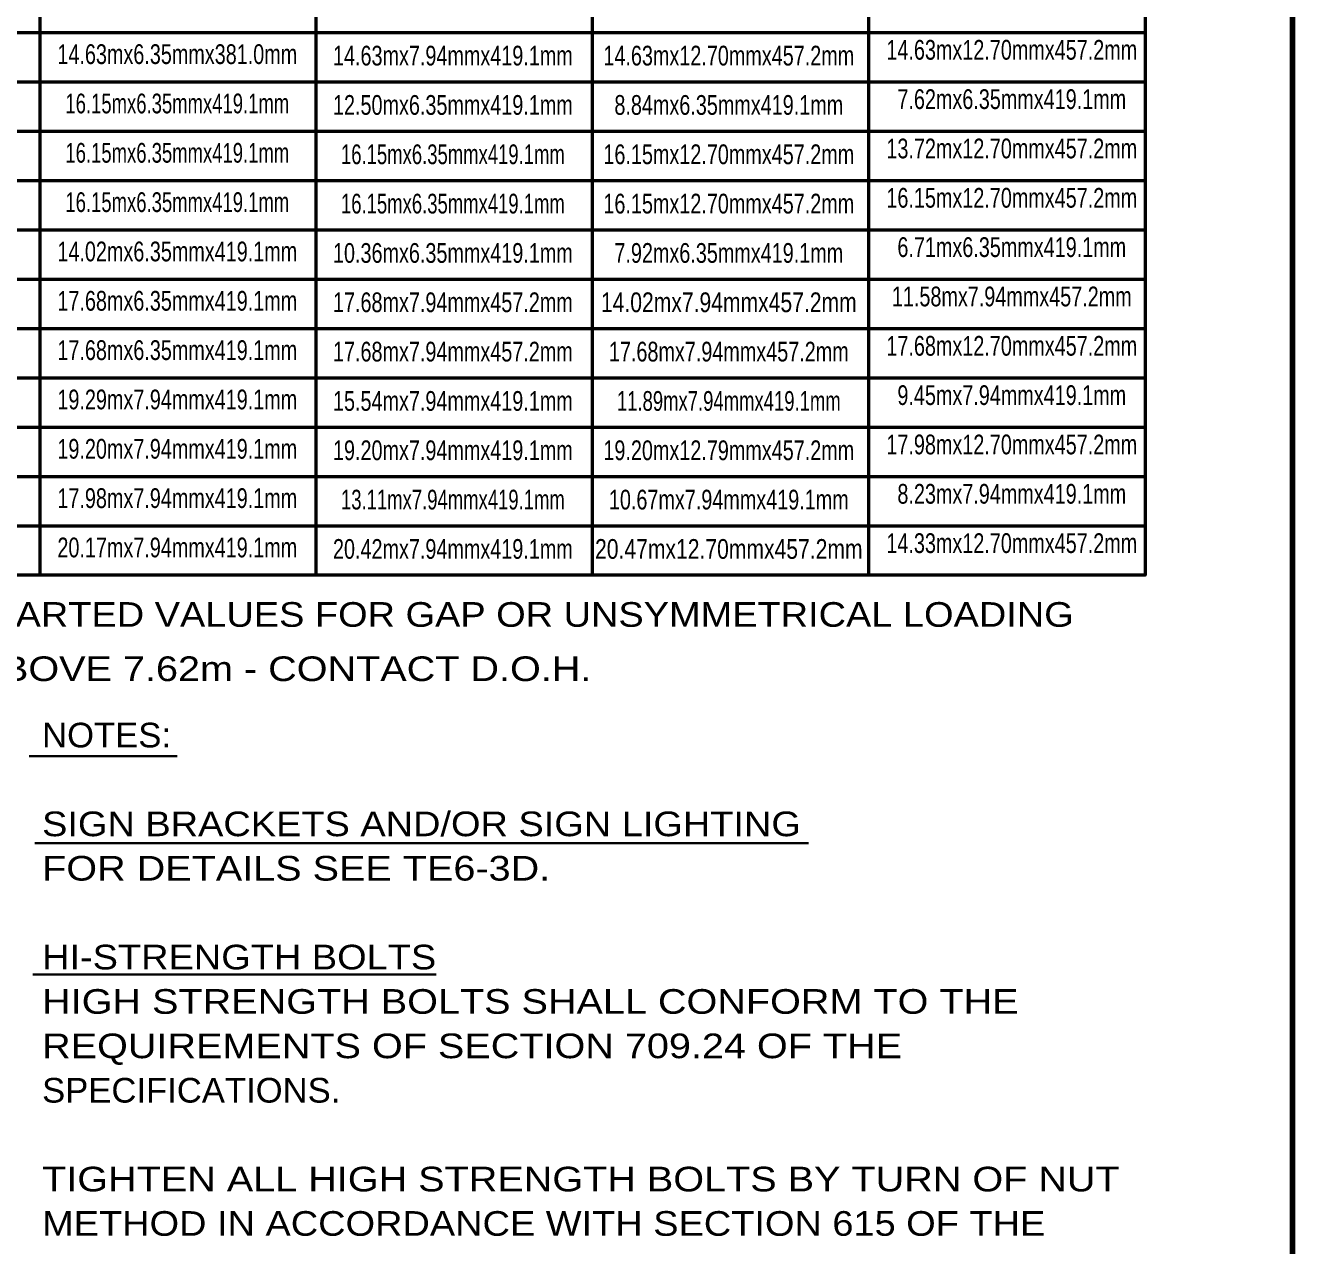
# Model space of a CAD drawing. Extents: x -34 to 822, y -23 to 521.
# Drawn here: x 660.8 to 814.9, y 213.8 to 362.2 of the extents above; entities that cross this region are included whole.
import ezdxf
from ezdxf.enums import TextEntityAlignment as Align

# ---------------------------------------------------------------- set-up
doc = ezdxf.new("R2010")
doc.units = 0
doc.header["$LTSCALE"] = 1.2
doc.layers.add('1', color=7, linetype='Continuous', lineweight=35)

msp = doc.modelspace()

# ---------------------------------------------------------------- linework, layer by layer
at = {"layer": '1', "lineweight": 158}
msp.add_line((814.9, -11.36), (814.9, 514.74), dxfattribs=at)
at = {"layer": '1', "lineweight": 13}
msp.add_line((814.9, -11.36), (814.9, 514.74), dxfattribs=at)
at = {"layer": '1', "lineweight": 53}
for p, q in [((662.554, 295.349), (662.554, 458.549)), ((696.154, 295.349), (696.154, 458.549)), ((729.754, 295.349), (729.754, 458.549)), ((763.354, 295.349), (763.354, 458.549)), ((595.354, 361.349), (796.954, 361.349)), ((577.354, 355.349), (796.954, 355.349)), ((595.354, 349.349), (796.954, 349.349)), ((595.354, 343.349), (796.954, 343.349)), ((577.354, 337.349), (796.954, 337.349)), ((595.354, 331.349), (796.954, 331.349)), ((595.354, 325.349), (796.954, 325.349)), ((577.354, 319.349), (796.954, 319.349)), ((595.354, 313.349), (796.954, 313.349)), ((577.354, 307.349), (796.954, 307.349)), ((595.354, 301.349), (796.954, 301.349))]:
    msp.add_line(p, q, dxfattribs=at)
at = {"layer": '1'}
for p, q in [((661.23, 273.35), (679.232, 273.35)), ((661.905, 262.77), (756.005, 262.77)), ((661.68, 246.788), (710.736, 246.788))]:
    msp.add_line(p, q, dxfattribs=at)
at = {"layer": '1', "lineweight": 53}
msp.add_lwpolyline([(577.354, 482.549), (796.954, 482.549), (796.954, 295.349), (577.354, 295.349)], close=True, dxfattribs=at)

# ---------------------------------------------------------------- texts
at = {"layer": '1'}
for s, width, p in [('14.63mx6.35mmx381.0mm', 0.75, (679.25, 357.518)), ('14.63mx7.94mmx419.1mm', 0.75, (712.766, 357.338)), ('14.63mx12.70mmx457.2mm', 0.75, (746.324, 357.338)), ('14.63mx12.70mmx457.2mm', 0.75, (780.742, 358.045)), ('16.15mx6.35mmx419.1mm', 0.7, (679.25, 351.518)), ('12.50mx6.35mmx419.1mm', 0.75, (712.766, 351.338)), ('8.84mx6.35mmx419.1mm', 0.75, (746.324, 351.338)), ('7.62mx6.35mmx419.1mm', 0.75, (780.742, 352.045)), ('13.72mx12.70mmx457.2mm', 0.75, (780.742, 346.045)), ('16.15mx6.35mmx419.1mm', 0.7, (679.25, 345.518)), ('16.15mx6.35mmx419.1mm', 0.7, (712.766, 345.338)), ('16.15mx12.70mmx457.2mm', 0.75, (746.324, 345.338)), ('16.15mx12.70mmx457.2mm', 0.75, (780.742, 340.045)), ('16.15mx6.35mmx419.1mm', 0.7, (679.25, 339.518)), ('16.15mx6.35mmx419.1mm', 0.7, (712.766, 339.338)), ('16.15mx12.70mmx457.2mm', 0.75, (746.324, 339.338)), ('6.71mx6.35mmx419.1mm', 0.75, (780.742, 334.045)), ('14.02mx6.35mmx419.1mm', 0.75, (679.25, 333.518)), ('10.36mx6.35mmx419.1mm', 0.75, (712.766, 333.338)), ('7.92mx6.35mmx419.1mm', 0.75, (746.324, 333.338)), ('17.68mx6.35mmx419.1mm', 0.75, (679.25, 327.518)), ('11.58mx7.94mmx457.2mm', 0.75, (780.742, 328.045)), ('17.68mx7.94mmx457.2mm', 0.75, (712.766, 327.338)), ('14.02mx7.94mmx457.2mm', 0.8, (746.324, 327.338)), ('17.68mx6.35mmx419.1mm', 0.75, (679.25, 321.518)), ('17.68mx7.94mmx457.2mm', 0.75, (712.766, 321.338)), ('17.68mx7.94mmx457.2mm', 0.75, (746.324, 321.338)), ('17.68mx12.70mmx457.2mm', 0.75, (780.742, 322.045)), ('19.29mx7.94mmx419.1mm', 0.75, (679.25, 315.518)), ('15.54mx7.94mmx419.1mm', 0.75, (712.766, 315.338)), ('11.89mx7.94mmx419.1mm', 0.7, (746.324, 315.338)), ('9.45mx7.94mmx419.1mm', 0.75, (780.742, 316.045)), ('19.20mx7.94mmx419.1mm', 0.75, (679.25, 309.518)), ('19.20mx7.94mmx419.1mm', 0.75, (712.766, 309.338)), ('19.20mx12.79mmx457.2mm', 0.75, (746.324, 309.338)), ('17.98mx12.70mmx457.2mm', 0.75, (780.742, 310.045)), ('17.98mx7.94mmx419.1mm', 0.75, (679.25, 303.518)), ('13.11mx7.94mmx419.1mm', 0.7, (712.766, 303.338)), ('10.67mx7.94mmx419.1mm', 0.75, (746.324, 303.338)), ('8.23mx7.94mmx419.1mm', 0.75, (780.742, 304.045)), ('20.17mx7.94mmx419.1mm', 0.75, (679.25, 297.518)), ('20.42mx7.94mmx419.1mm', 0.75, (712.766, 297.338)), ('20.47mx12.70mmx457.2mm', 0.8, (746.324, 297.338)), ('14.33mx12.70mmx457.2mm', 0.75, (780.742, 298.045))]:
    msp.add_text(s, height=2.4, dxfattribs=dict(at, width=width)).set_placement(p, align=Align.CENTER)
for s, width, p in [('INTERPOLATE:  BETWEEN CHARTED VALUES FOR GAP OR UNSYMMETRICAL LOADING', 1.15, (592.936, 289.07)), ('FOR MOUNTING HEIGHTS ABOVE 7.62m - CONTACT D.O.H.', 1.2, (592.936, 282.47)), ('NOTES:', 1.05, (662.806, 274.402)), ('SIGN BRACKETS AND/OR SIGN LIGHTING', 1.15, (662.806, 263.602)), ('FOR DETAILS SEE TE6-3D.', 1.2, (662.806, 258.202)), ('HI-STRENGTH BOLTS', 1.15, (662.806, 247.402)), ('HIGH STRENGTH BOLTS SHALL CONFORM TO THE', 1.2, (662.806, 242.002)), ('REQUIREMENTS OF SECTION 709.24 OF THE', 1.2, (662.806, 236.602)), ('SPECIFICATIONS.', 1.05, (662.806, 231.202)), ('TIGHTEN ALL HIGH STRENGTH BOLTS BY TURN OF NUT', 1.2, (662.806, 220.402)), ('METHOD IN ACCORDANCE WITH SECTION 615 OF THE', 1.15, (662.806, 215.002))]:
    msp.add_text(s, height=3, dxfattribs=dict(at, width=width)).set_placement(p)

doc.saveas('drawing.dxf')
